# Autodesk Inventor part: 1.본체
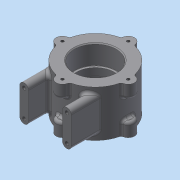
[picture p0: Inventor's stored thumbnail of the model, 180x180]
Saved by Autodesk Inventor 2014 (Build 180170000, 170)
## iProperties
Created: 2015-03
Part Number: 1.본체
Material: 일반
Document SubType Name: Modeling
Designer: net
Density: 1 g/cm^3
Appearance: 기본값
Author: net
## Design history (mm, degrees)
sketch "스케치1"
  geometry: C1 r 37 at (0, 0); 1 further point
  constraints: 1 centre point, 1 coincident
  dimensions: "d0" = 74 diameter of C1
extrude "돌출1" new body sketch "스케치1" stored distance "d1" = 52; taper "d2" = 0 deg
sketch "스케치2"
  geometry: C1 r 7 at (0, 37); C2 r 7 at (37, 0); C3 r 7 at (0, -37); C4 r 7 at (-37, 0); A1 r 37 centre (0, 0) between (0, 37) and (37, 0) reference
  constraints: 4 centre point, 4 point on circle, 3 equal radius, 2 horizontal alignment, 2 vertical alignment
  dimensions: "d3" = 14 diameter of C1
extrude "돌출2" join sketch "스케치2" distance "d4" = 15; taper "d5" = 0 deg
hole "구멍1" diameter "d8" = 3.242; stored, may be unused: countersink angle "d12" = 90 deg, drill point angle "d14" = 118 deg; dims "d6" = 10, "d7" = 10, "d9" = 8, "d10" = 4, "d11" = 2, "d13" = 11
node "작업 평면1"
node "작업 평면2"
sketch "스케치3"
  geometry: L1 (0, 0)-(-26.163, 26.163); L2 (0, 0)-(-37, 0); A1 r 37 centre (0, 0) between (-6.969, 36.338) and (-36.338, 6.969) reference; 2 further points
  constraints: 4 end point, 1 coincident, 1 horizontal, 1 point on circle
  dimensions: "d18" = 45 deg angle of L2 L1
node "작업 평면3"
sketch "스케치4"
  geometry: L1 (-20.767, -26)-(20.767, -26) reference; 2 further points
  constraints: 1 coincident, 1 other
  dimensions: "d92" = 26 distance from line of point (0, 0) L1
feature "엠보싱1" sketch "스케치4" dims "d1" = 52, "d19" = 0.5, "d20" = 0
node "작업 평면4"
sketch "스케치5"
  geometry: L1 (19, -15)-(19, 15); L2 (29, -15)-(29, 15); L3 (-29, 15)-(-29, -15); L4 (-19, -15)-(-19, 15); A1 r 5 centre (24, 15) between (19, 15) and (29, 15); A2 r 5 centre (24, -15) between (19, -15) and (29, -15); A3 r 5 centre (-24, -15) between (-29, -15) and (-19, -15); A4 r 5 centre (-24, 15) between (-29, 15) and (-19, 15); 2 further points
  constraints: 8 end point, 8 point on circle, 7 tangent, 4 centre point, 2 vertical alignment, 1 horizontal alignment, 1 midpoint, 1 parallel
  dimensions: "d22" = 10 diameter of A1; "d23" = 10 diameter of A2; "d24" = 30 distance of A2.centre A1.centre; "d25" = 24 horizontal distance of A2.centre point (0, 0); "d29" = 10 diameter of A4; "d30" = 10 diameter of A3; "d31" = 30 distance of A3.centre A4.centre; "d32" = 24 horizontal distance of point (0, 0) A3.centre; "d35" = 24.20744 distance of L4.end point (0, 0)
extrude "돌출3" join sketch "스케치5" stored distance "d36" = 15; taper "d37" = 0 deg
hole "구멍2" diameter "d40" = 4.134; stored, may be unused: countersink angle "d44" = 90 deg, drill point angle "d46" = 118 deg; dims "d38" = 10, "d39" = 10, "d41" = 6, "d42" = 4, "d43" = 2, "d45" = 8
hole "구멍3" diameter "d49" = 4.134; stored, may be unused: countersink angle "d53" = 90 deg, drill point angle "d55" = 118 deg; dims "d47" = 10, "d48" = 10, "d50" = 6, "d51" = 4, "d52" = 2, "d54" = 8
hole "구멍4" diameter "d58" = 4.134; stored, may be unused: countersink angle "d62" = 90 deg, drill point angle "d64" = 118 deg; dims "d56" = 10, "d57" = 10, "d59" = 6, "d60" = 4, "d61" = 2, "d63" = 8
hole "구멍5" diameter "d67" = 4.134; stored, may be unused: countersink angle "d71" = 90 deg, drill point angle "d73" = 118 deg; dims "d65" = 10, "d66" = 10, "d68" = 6, "d69" = 4, "d70" = 2, "d72" = 8
hole "구멍6" diameter "d76" = 47; stored, may be unused: countersink angle "d80" = 90 deg, drill point angle "d82" = 0 deg; dims "d74" = 10, "d75" = 10, "d77" = 6, "d78" = 4, "d79" = 2, "d81" = 22
hole "구멍7" diameter "d85" = 42; stored, may be unused: countersink angle "d89" = 90 deg, drill point angle "d91" = 0 deg; dims "d83" = 10, "d84" = 10, "d86" = 6, "d87" = 47, "d88" = 22, "d90" = 50
fillet "모깎기1" dims "d93" = 0.3
chamfer "모따기1" distance "d94" = 1; stored, may be unused: second distance "d95" = 2, angle "d96" = 45 deg
fillet "모깎기2" dims "d97" = 3
fillet "모깎기3" dims "d98" = 3
fillet "모깎기4" dims "d99" = 3
fillet "모깎기5" dims "d100" = 3
fillet "모깎기6" dims "d101" = 3
fillet "모깎기7" dims "d102" = 3
node "솔리드1"
pattern_circular "원형 패턴1" dims angle "d16" = 360 deg
mirror "대칭1"
other parameters: "d21" = -56
